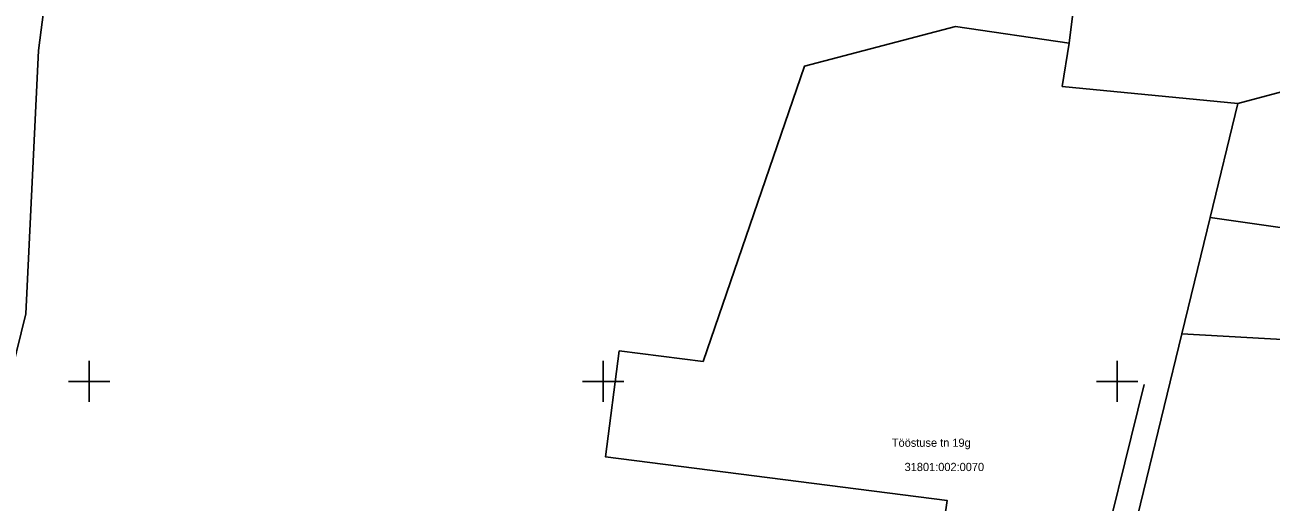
# Model space of a CAD drawing. Extents: x 542320 to 543602, y 6558748 to 6559969.
# Drawn here: x 542893.7 to 543015, y 6559838.3 to 6559884.7 of the extents above; entities that cross this region are included whole.
import ezdxf

# ---------------------------------------------------------------- set-up
doc = ezdxf.new("R2010")
doc.units = 0
for name, color, linetype in [('PIIR', 7, 'Continuous'), ('VORK', 7, 'Continuous'), ('VTRASS', 7, 'Continuous')]:
    doc.layers.add(name, color=color, linetype=linetype)

# ---------------------------------------------------------------- blocks, each defined once
blk = doc.blocks.new('VKORIS')
for p, q in [((0, 4), (0, -4)), ((-4, 0), (4, 0))]:
    blk.add_line(p, q)

msp = doc.modelspace()

# ---------------------------------------------------------------- linework, layer by layer
at = {"layer": 'PIIR'}
for points in [[(542895.08, 6559882.19), (542906.28, 6559968.94)], [(543002.19, 6559938.61), (542995.32, 6559882.88), (542984.27, 6559884.51), (542969.58, 6559880.67), (542959.71, 6559851.95), (542951.57, 6559852.97), (542950.23, 6559842.65), (542983.46, 6559838.42), (542982.04, 6559828.61), (542999.42, 6559826.35), (542995.62, 6559810.72), (542945.79, 6559811), (542937.03, 6559811.18), (542940.09, 6559774.59), (542939.23, 6559774.33), (542936.93, 6559773.44), (542936.99, 6559774.91), (542930.97, 6559773.19), (542914.12, 6559772.15), (542904.4, 6559772.44), (542898.6, 6559772.95), (542894.88, 6559773.72), (542892.18, 6559776.92)], [(542995.62, 6559810.72), (542999.42, 6559826.35), (543006.28, 6559854.63), (543022.96, 6559853.69), (543024.02, 6559863.81), (543009.03, 6559865.93), (543011.73, 6559877.03), (543035.19, 6559883.28), (543069.03, 6559887.03), (543076.83, 6559836.49), (543078.56, 6559825.31), (543011.79, 6559810.61), (542995.62, 6559810.72)], [(542950.23, 6559842.65), (542951.57, 6559852.97), (542959.71, 6559851.95), (542969.58, 6559880.67), (542984.27, 6559884.51), (542995.32, 6559882.88), (542994.65, 6559878.68), (543011.73, 6559877.03), (543009.03, 6559865.93), (543006.28, 6559854.63), (542999.42, 6559826.35), (542982.04, 6559828.61), (542983.46, 6559838.42), (542950.23, 6559842.65)], [(542885.2, 6559821.58), (542893.84, 6559856.58), (542895.08, 6559882.19)]]:
    msp.add_lwpolyline(points, dxfattribs=at)
at = {"layer": 'VTRASS'}
msp.add_lwpolyline([(543002.61, 6559849.71), (542997.59, 6559829.35), (542995.8, 6559810), (542992.4, 6559762.21)], dxfattribs=at)

# ---------------------------------------------------------------- block references
at = {"layer": 'VORK', "xscale": 0.5, "yscale": 0.5}
for p in [(542900, 6559850), (542950, 6559850), (543000, 6559850)]:
    msp.add_blockref('VKORIS', p, dxfattribs=at)

# ---------------------------------------------------------------- texts
at = {"layer": 'PIIR'}
for s, p in [('Tööstuse tn 19g', (542978.08, 6559843.64)), ('31801:002:0070', (542979.32, 6559841.28))]:
    msp.add_text(s, height=0.8, dxfattribs=at).set_placement(p)

doc.saveas('drawing.dxf')
